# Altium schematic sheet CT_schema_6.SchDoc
size 479 x 328 mm
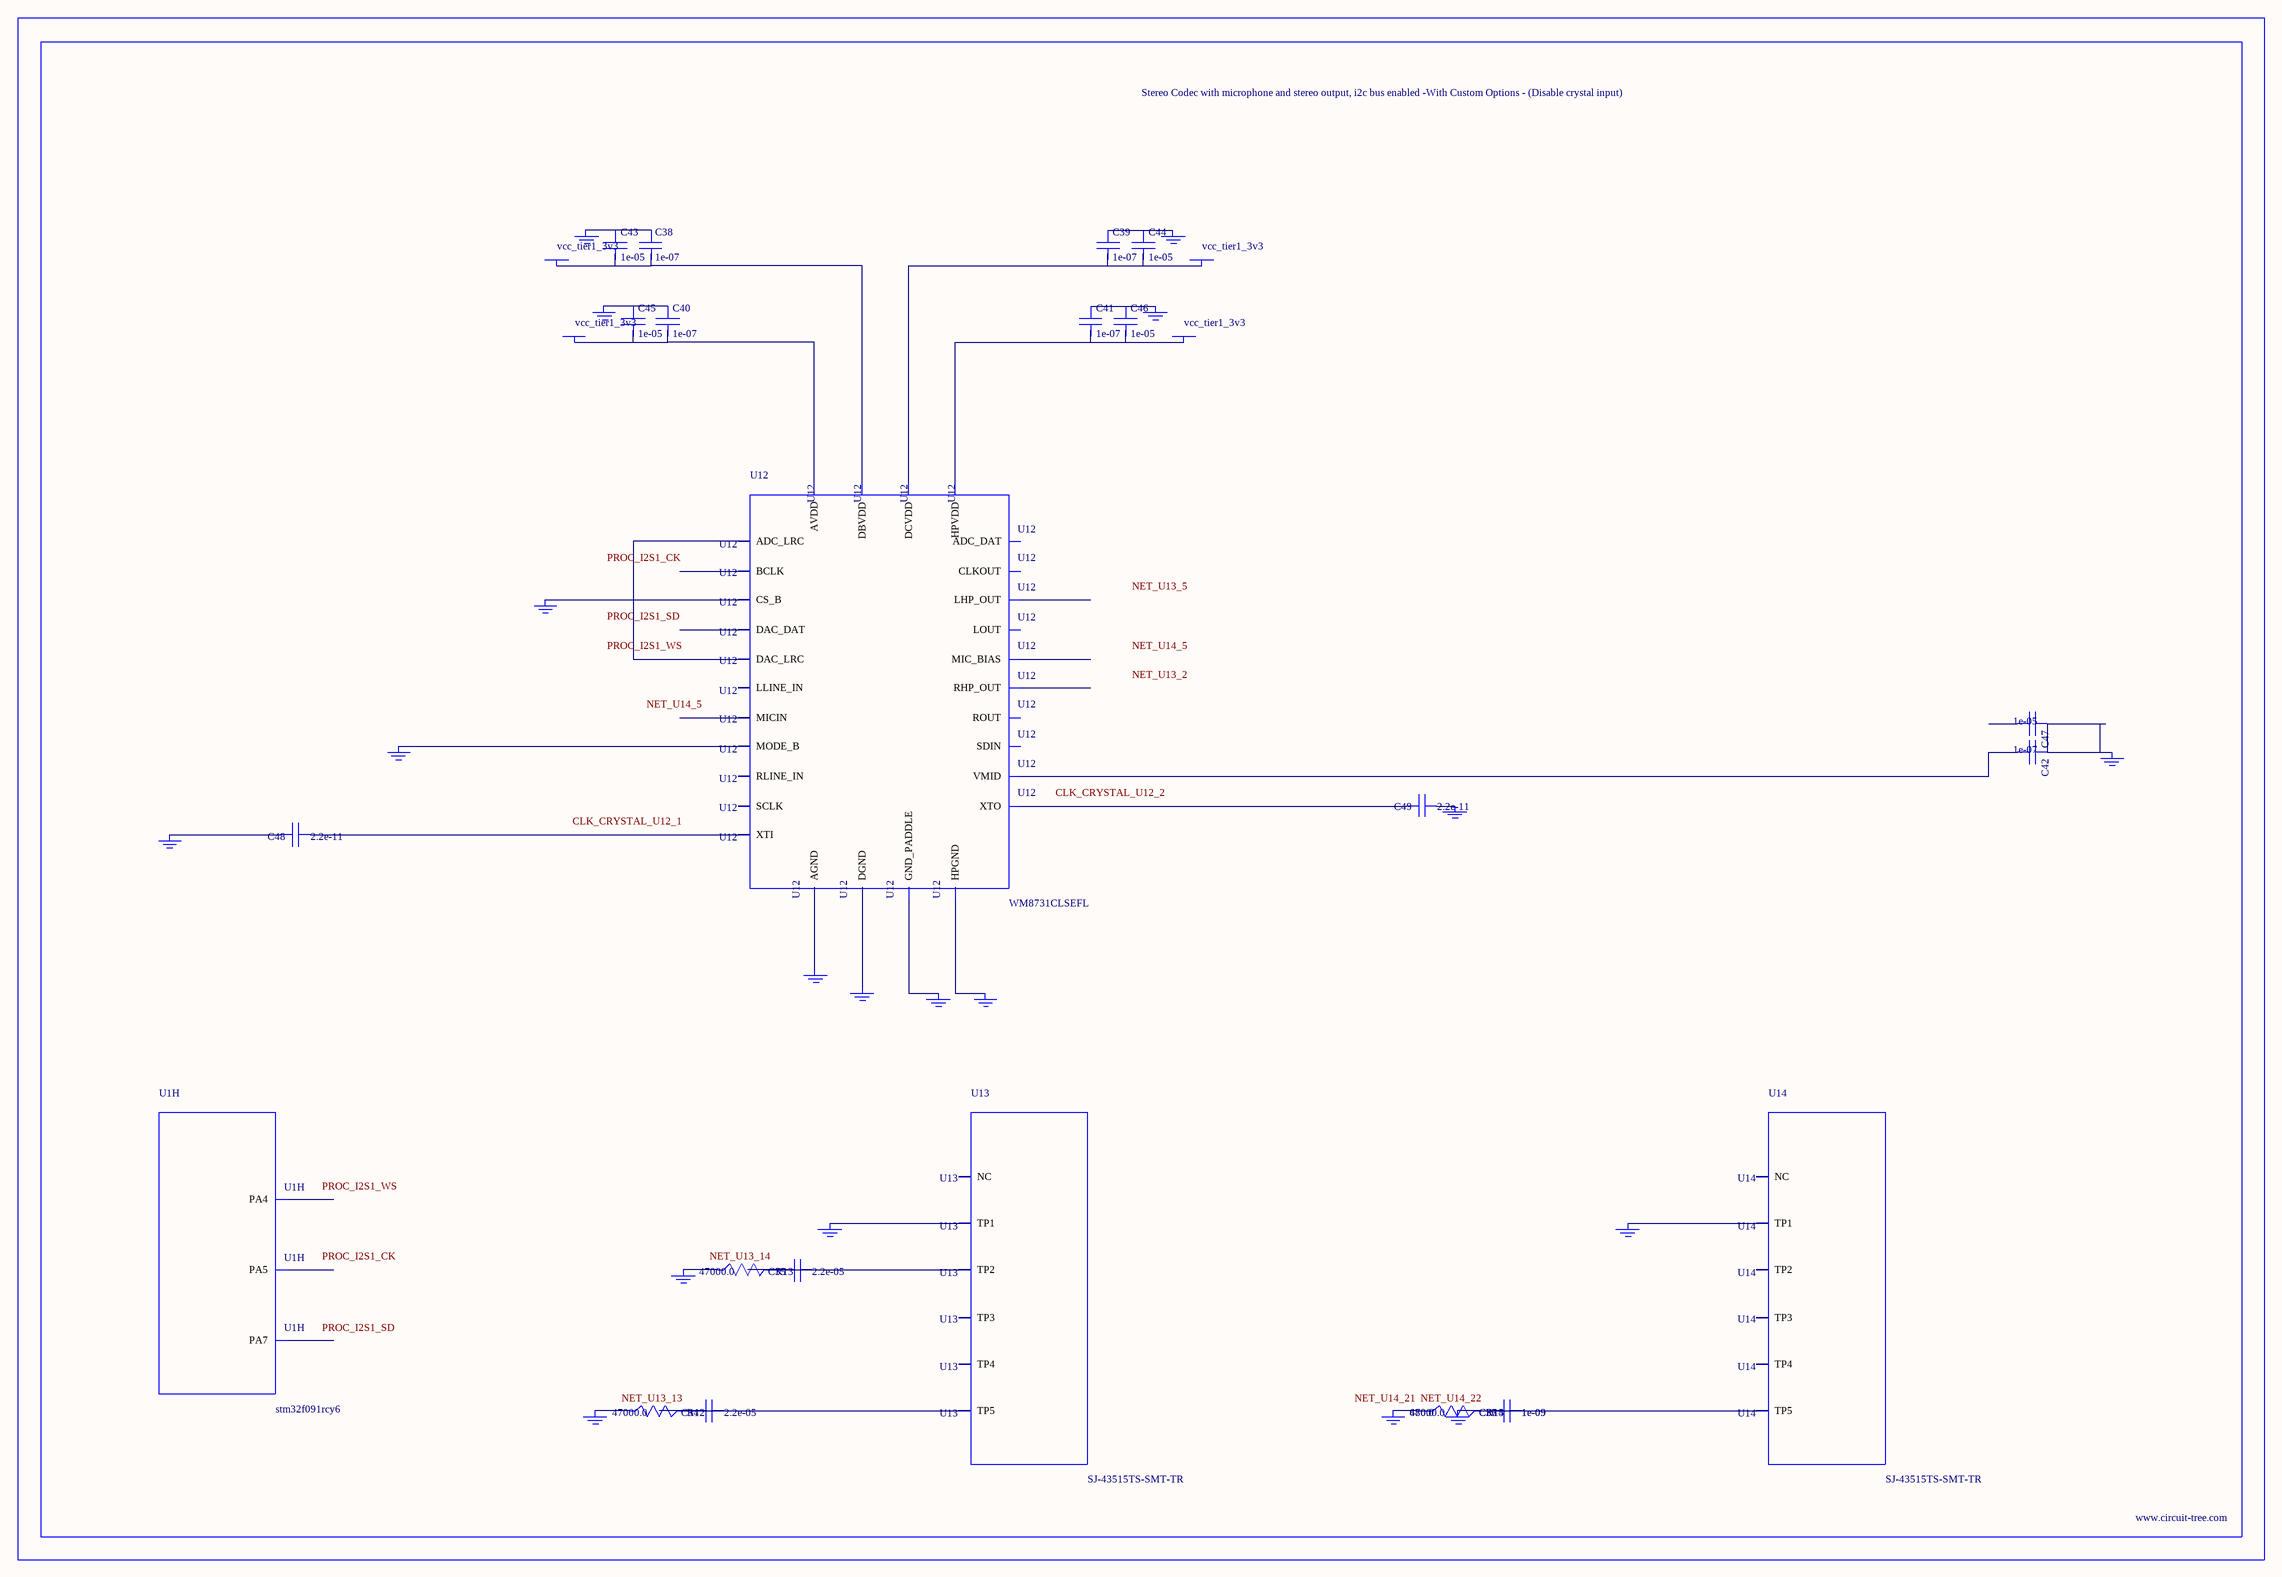
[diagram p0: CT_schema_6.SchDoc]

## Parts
BORDER5  (no value)
C34  2.2e-05  [C1210]
C35  2.2e-05  [C1210]
C36  1e-09  [C0402]
C37  1e-09  [C0402]
C38  1e-07  [C0402]
C39  1e-07  [C0402]
C40  1e-07  [C0402]
C41  1e-07  [C0402]
C42  1e-07  [C0402]
C43  1e-05  [C0805]
C44  1e-05  [C0805]
C45  1e-05  [C0805]
C46  1e-05  [C0805]
C47  1e-05  [C0805]
C48  2.2e-11  [C0402]
C49  2.2e-11  [C0402]
GND_INSTANCE_5_0  (no value)
GND_INSTANCE_5_1  (no value)
GND_INSTANCE_5_2  (no value)
GND_INSTANCE_5_3  (no value)
GND_INSTANCE_5_4  (no value)
GND_INSTANCE_5_5  (no value)
GND_INSTANCE_5_6  (no value)
GND_INSTANCE_5_7  (no value)
GND_INSTANCE_5_8  (no value)
GND_INSTANCE_5_9  (no value)
GND_INSTANCE_5_10  (no value)
GND_INSTANCE_5_11  (no value)
GND_INSTANCE_5_12  (no value)
GND_INSTANCE_5_13  (no value)
GND_INSTANCE_5_14  (no value)
GND_INSTANCE_5_15  (no value)
GND_INSTANCE_5_16  (no value)
GND_INSTANCE_5_17  (no value)
GND_INSTANCE_5_18  (no value)
POWER_INSTANCE_5_0  vcc_tier1_3v3
POWER_INSTANCE_5_1  vcc_tier1_3v3
POWER_INSTANCE_5_2  vcc_tier1_3v3
POWER_INSTANCE_5_3  vcc_tier1_3v3
R12  47000.0  [R0603]
R13  47000.0  [R0603]
R14  47000.0  [R0603]
R15  680.0  [R0603]
U1  stm32f091rcy6  [WLCSP64]  (part H of 8)
U12  WM8731CLSEFL  [QFN-28]
U13  SJ-43515TS-SMT-TR  [SJ-43515TS-SMT-TR]
U14  SJ-43515TS-SMT-TR  [SJ-43515TS-SMT-TR]

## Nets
NetC34_1: C34.1 C34.2 R12.2 U13.5(TP5)
NetC35_1: C35.1 C35.2 R13.2 U13.2(TP2)
NetC36_1: C36.1 C36.2 C37.1 C37.2 GND_INSTANCE_5_18.0(GND) R14.2 R15.2 U14.5(TP5)
NetC38_1: C38.1 C43.1 GND_INSTANCE_5_3.0(GND)
NetC38_2: C38.2 C43.2 POWER_INSTANCE_5_1.0(PWR) U12.5(DBVDD)
NetC39_1: C39.1 C44.1 GND_INSTANCE_5_2.0(GND)
NetC39_2: C39.2 C44.2 POWER_INSTANCE_5_0.0(PWR) U12.3(DCVDD)
NetC40_1: C40.1 C45.1 GND_INSTANCE_5_6.0(GND)
NetC40_2: C40.2 C45.2 POWER_INSTANCE_5_3.0(PWR) U12.18(AVDD)
NetC41_1: C41.1 C46.1 GND_INSTANCE_5_4.0(GND)
NetC41_2: C41.2 C46.2 POWER_INSTANCE_5_2.0(PWR) U12.12(HPVDD)
NetC42_1: C42.1 C47.1 GND_INSTANCE_5_7.0(GND)
NetC42_2: C42.2 U12.20(VMID)
NetC48_1: C48.1 U12.1(XTI)
NetC48_2: C48.2 GND_INSTANCE_5_0.0(GND)
NetC49_1: C49.1 GND_INSTANCE_5_1.0(GND)
NetC49_2: C49.2 U12.2(XTO)
NetGND_INSTANCE_5_5_0: GND_INSTANCE_5_5.0(GND) U12.15(HPGND)
NetGND_INSTANCE_5_8_0: GND_INSTANCE_5_8.0(GND) U12.25(MODE_B)
NetGND_INSTANCE_5_9_0: GND_INSTANCE_5_9.0(GND) U12.26(CS_B)
NetGND_INSTANCE_5_10_0: GND_INSTANCE_5_10.0(GND) U12.29(GND_PADDLE)
NetGND_INSTANCE_5_11_0: GND_INSTANCE_5_11.0(GND) U12.4(DGND)
NetGND_INSTANCE_5_12_0: GND_INSTANCE_5_12.0(GND) U12.19(AGND)
NetGND_INSTANCE_5_13_0: GND_INSTANCE_5_13.0(GND) U13.1(TP1)
NetGND_INSTANCE_5_14_0: GND_INSTANCE_5_14.0(GND) R13.1
NetGND_INSTANCE_5_15_0: GND_INSTANCE_5_15.0(GND) R12.1
NetGND_INSTANCE_5_16_0: GND_INSTANCE_5_16.0(GND) U14.1(TP1)
NetGND_INSTANCE_5_17_0: GND_INSTANCE_5_17.0(GND) R14.1 R15.1
NetU12_9: U12.9(DAC_LRC) U12.11(ADC_LRC)

Not connected (* = marked no-connect by the designer): C47 2; U1 E4(PA7) F5(PA5) H6(PA4); U12 6(CLKOUT) 7(BCLK) 8(DAC_DAT) 10(ADC_DAT) 13(LHP_OUT) 14(RHP_OUT) 16(LOUT) 17(ROUT) 21(MIC_BIAS) 22(MICIN) 23(RLINE_IN) 24(LLINE_IN) 27(SDIN) 28(SCLK); U13 3(TP3) 4(TP4) 6(NC); U14 2(TP2) 3(TP3) 4(TP4) 6(NC)

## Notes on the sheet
- Labels drawn without touching a wire or pin: CLK_CRYSTAL_U12_1, CLK_CRYSTAL_U12_2, NET_U13_2, NET_U13_5, NET_U13_13, NET_U13_14, NET_U14_5, NET_U14_21, NET_U14_22, PROC_I2S1_CK, PROC_I2S1_SD, PROC_I2S1_WS

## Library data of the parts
BORDER5 = BORDER_PAGE5
C34 C35 = C1210C224K5RACTU
C36 C37 = C0402C102K3RAC
C38-C42 = C0402C104K3RACTU
C43-C47 = C0805C106K8RACTU
C48 C49 = C0402C220K3RAC
GND_INSTANCE_5_0-GND_INSTANCE_5_18 = GND
POWER_INSTANCE_5_0-POWER_INSTANCE_5_3 = PWR
R12-R14 = RC0603JR-0747KL
R15 = RC0603JR-07680RL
